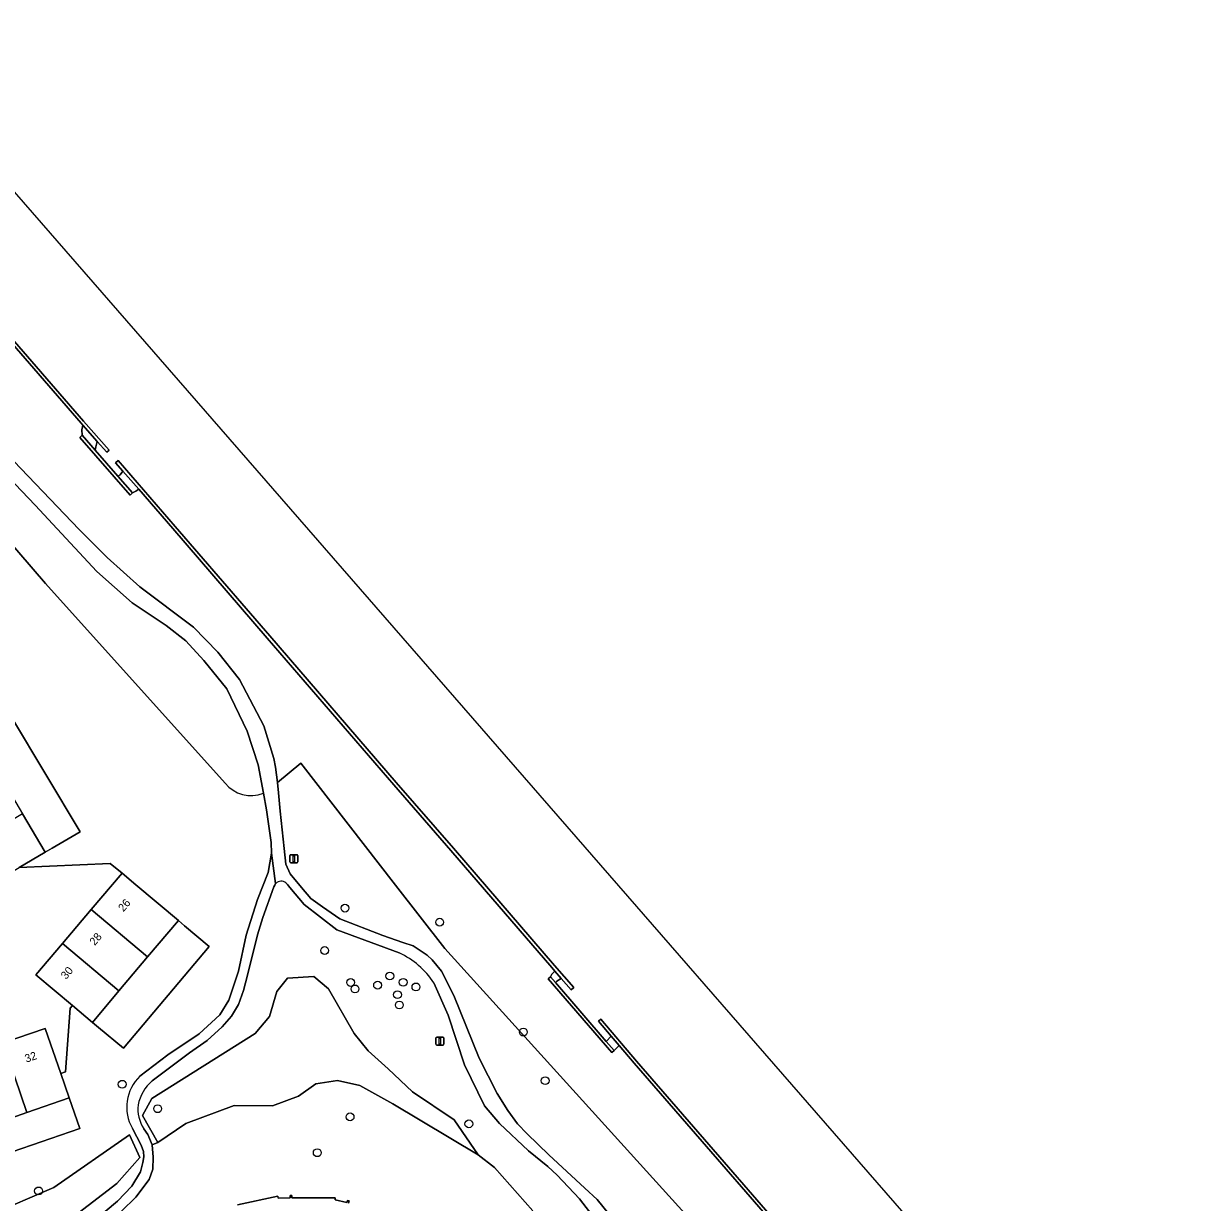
# Model space of a CAD drawing. Extents: x 156661 to 157576, y 383570 to 384425.
# Drawn here: x 157016.4 to 157162.1, y 384130.7 to 384278 of the extents above; entities that cross this region are included whole.
import ezdxf

# ---------------------------------------------------------------- set-up
doc = ezdxf.new("R2010")
doc.units = 0
for name, color, linetype in [('IMGEO_Afsluitpaal', 7, 'Continuous'), ('IMGEO_Boom', 7, 'Continuous'), ('IMGEO_Erf', 7, 'Continuous'), ('IMGEO_Greppel_droge_sloot', 7, 'Continuous'), ('IMGEO_Groenvoorziening', 7, 'Continuous'), ('IMGEO_Houtwal', 7, 'Continuous'), ('IMGEO_Kademuur', 7, 'Continuous'), ('IMGEO_Muur', 7, 'Continuous'), ('IMGEO_Oever', 7, 'Continuous'), ('IMGEO_Pand', 7, 'Continuous'), ('IMGEO_Pand_nummerreeks', 7, 'Continuous'), ('IMGEO_Verkeersbordpaal', 7, 'Continuous'), ('IMGEO_Voetpad_halfverhard', 7, 'Continuous'), ('IMGEO_Waterloop', 7, 'Continuous')]:
    doc.layers.add(name, color=color, linetype=linetype)

msp = doc.modelspace()

# ---------------------------------------------------------------- linework, layer by layer
at = {"layer": 'IMGEO_Afsluitpaal'}
for p, q in [((157067.89, 384150.45), (157067.89, 384151.24)), ((157067.89, 384151.24), (157067.89, 384150.45)), ((157067.99, 384151.34), (157068.78, 384151.34)), ((157068.78, 384151.34), (157067.99, 384151.34)), ((157068.78, 384150.35), (157067.99, 384150.35)), ((157067.99, 384150.35), (157068.78, 384150.35)), ((157068.88, 384151.24), (157068.88, 384150.45)), ((157068.88, 384150.45), (157068.88, 384151.24))]:
    msp.add_line(p, q, dxfattribs=at)
msp.add_lwpolyline([(157068.31, 384151.22), (157068.46, 384151.22), (157068.46, 384150.47), (157068.31, 384150.47), (157068.31, 384151.22)], dxfattribs=at)
for centre, start, end in [((157067.99, 384151.24), 90, 180), ((157067.99, 384151.24), 90, 180), ((157067.99, 384150.45), 180, 270), ((157067.99, 384150.45), 180, 270), ((157068.78, 384151.24), 0, 90), ((157068.78, 384151.24), 360, 90), ((157068.78, 384150.45), 270, 0), ((157068.78, 384150.45), 270, 0)]:
    msp.add_arc(centre, 0.1, start, end, dxfattribs=at)
at = {"layer": 'IMGEO_Boom'}
for centre in [(157056.52, 384167.47), (157068.36, 384165.71), (157053.98, 384162.17), (157062.13, 384158.98), (157057.24, 384158.18), (157057.77, 384157.37), (157060.6, 384157.84), (157063.8, 384158.2), (157065.39, 384157.62), (157063.08, 384156.65), (157063.31, 384155.36), (157078.82, 384151.98), (157028.68, 384145.46), (157081.55, 384145.9), (157033.11, 384142.4), (157057.16, 384141.38), (157072.01, 384140.51), (157053.06, 384136.9), (157018.23, 384132.13)]:
    msp.add_circle(centre, 0.489, dxfattribs=at)
at = {"layer": 'IMGEO_Erf'}
for points in [[(157010.52, 384188.78), (157013.37, 384184), (157016.22, 384179.24), (157019.06, 384174.47), (157019.93, 384174.98), (157023.41, 384177.02), (157014.84, 384191.35), (157011.39, 384189.29)], [(157025.73, 384152.55), (157028.83, 384149.97), (157039.56, 384162.69), (157036.48, 384165.27), (157035.7, 384165.92), (157031.86, 384161.37), (157028.28, 384157.12), (157024.96, 384153.19)], [(157006.66, 384137.36), (157007.65, 384134.51), (157023.4, 384139.95), (157022.39, 384142.82), (157022.06, 384143.77), (157016.78, 384141.93), (157011.54, 384140.11), (157006.33, 384138.3)]]:
    msp.add_lwpolyline(points, close=True, dxfattribs=at)
for points in [[(157013.79, 384150.62), (157019.05, 384152.43), (157021, 384146.82), (157021.59, 384147.02), (157022.19, 384154.96), (157022.46, 384155.29), (157017.9, 384159.12), (157021.23, 384163.05), (157024.82, 384167.28), (157028.66, 384171.82), (157027.18, 384173.06), (157015.79, 384172.54)], [(157056.97, 384130.62), (157057.03, 384130.89), (157056.82, 384130.94), (157056.77, 384130.67), (157055.29, 384131), (157055.3, 384131.25), (157049.9, 384131.27), (157049.89, 384131.54), (157049.69, 384131.54), (157049.69, 384131.27), (157048.19, 384131.21), (157048.13, 384131.48), (157043.1, 384130.38)]]:
    msp.add_lwpolyline(points, dxfattribs=at)
at = {"layer": 'IMGEO_Greppel_droge_sloot'}
for points in [[(157057.67, 384151.81), (157054.48, 384157.38), (157052.61, 384158.91), (157049.33, 384158.7), (157048.02, 384157.03), (157047.08, 384153.92), (157045.3, 384151.79), (157032.38, 384143.68), (157031.2, 384141.56), (157033.15, 384138.17), (157036.64, 384140.57), (157042.69, 384142.82), (157047.48, 384142.77), (157050.7, 384143.97), (157052.89, 384145.51), (157055.6, 384145.94), (157058.37, 384145.32), (157062.52, 384143.02), (157073.18, 384136.62), (157070.19, 384141.01), (157064.98, 384144.51), (157061.93, 384147.4), (157059.42, 384149.63)], [(157020.85, 384127.54), (157028.03, 384133.07), (157030.88, 384136.29), (157029.6, 384139.14), (157020.14, 384132.57), (157011.98, 384129.07), (157003.7, 384126.69), (156998.76, 384122.64), (157001.81, 384121.29), (157011.12, 384122.68)]]:
    msp.add_lwpolyline(points, close=True, dxfattribs=at)
at = {"layer": 'IMGEO_Groenvoorziening'}
for points in [[(157041.54, 384183.09), (157019.08, 384208.03), (157004.98, 384224.39)], [(157014.84, 384191.35), (157023.41, 384177.02), (157019.93, 384174.98), (157019.06, 384174.47), (157015.79, 384172.54), (157027.18, 384173.06), (157028.66, 384171.82), (157030.4, 384170.36), (157035.7, 384165.92), (157036.48, 384165.27), (157039.56, 384162.69), (157028.83, 384149.97), (157025.73, 384152.55), (157024.96, 384153.19), (157022.46, 384155.29), (157022.19, 384154.96), (157021.59, 384147.02), (157021, 384146.82), (157022.06, 384143.77), (157022.39, 384142.82), (157023.4, 384139.95), (157007.65, 384134.51)], [(157107.42, 384120.01), (157068.99, 384162.42), (157062.85, 384170.34), (157051.02, 384185.6), (157048.07, 384183.16), (157048.23, 384181.88), (157048.43, 384179.6), (157048.92, 384174.93), (157049.15, 384172.98), (157049.67, 384171.76), (157051.08, 384170.04), (157052.24, 384168.68), (157053.73, 384167.61), (157055.86, 384166.15), (157061.25, 384164.03), (157063.77, 384163.18), (157065.06, 384162.74), (157065.94, 384162.17), (157066.81, 384161.58), (157067.44, 384161), (157068.6, 384159.57), (157070.14, 384156.57), (157073.28, 384148.7), (157075.53, 384144.3), (157076.88, 384142.2), (157078.09, 384140.5), (157079.31, 384139.27), (157082.01, 384136.66), (157086.51, 384132.48), (157088.05, 384131.05), (157091.04, 384127.35)], [(157030.9, 384146.49), (157034.38, 384149.12), (157038.31, 384151.74), (157040.89, 384154.15), (157042.01, 384155.98), (157043.22, 384159.6), (157044.19, 384164.08), (157045.6, 384168.56), (157046.91, 384171.94), (157047.33, 384174.35), (157047.28, 384175.68), (157046.71, 384179.73), (157046.32, 384181.83)], [(157063.29, 384161.87), (157055.52, 384164.74), (157051.44, 384167.93), (157049.63, 384170.05), (157049.48, 384170.25), (157049.32, 384170.44), (157049.14, 384170.61)], [(157047.86, 384170.54), (157047.74, 384170.34), (157047.65, 384170.11), (157046.26, 384166.31), (157045.57, 384164.15), (157044.32, 384159.07), (157043.82, 384157.18), (157043.23, 384155.44), (157042.36, 384153.96), (157041.18, 384152.62), (157039.28, 384150.91), (157037.1, 384149.38), (157032.43, 384145.87)], [(157031.39, 384139.9), (157031.89, 384139.17), (157032.41, 384137.9), (157033.15, 384138.17), (157031.2, 384141.56), (157032.38, 384143.68), (157045.3, 384151.79), (157047.08, 384153.92), (157048.02, 384157.03), (157049.33, 384158.7), (157052.61, 384158.91), (157054.48, 384157.38), (157057.67, 384151.81), (157059.42, 384149.63), (157061.93, 384147.4), (157064.98, 384144.51), (157070.19, 384141.01), (157073.18, 384136.62), (157075.19, 384135.05), (157079.98, 384129.64)], [(157209, 383933.11), (157208.19, 383936.36), (157188.23, 383963.43), (157190.29, 383965.09), (157189.95, 383965.49), (157191.63, 383966.17), (157192.42, 383966.8), (157192.61, 383966.56), (157193.69, 383967), (157194.04, 383967.21), (157214.31, 383979.84), (157095.74, 384121.39), (157093.38, 384123.17), (157089.79, 384126.55), (157087.81, 384128.62), (157085.82, 384131.16), (157083.05, 384134.11), (157081.87, 384135.17), (157079.45, 384137.14), (157075.84, 384140.54), (157073.95, 384142.77), (157071.48, 384147.87), (157069.43, 384154.1), (157067.64, 384158.13)], [(157079.98, 384129.64), (157075.19, 384135.05), (157073.18, 384136.62), (157062.52, 384143.02), (157058.37, 384145.32), (157055.6, 384145.94), (157052.89, 384145.51), (157050.7, 384143.97), (157047.48, 384142.77), (157042.69, 384142.82), (157036.64, 384140.57), (157033.15, 384138.17), (157032.41, 384137.9), (157032.57, 384136.35), (157032.5, 384134.85), (157032.04, 384133.57), (157030.38, 384131.36), (157028.58, 384129.59)], [(157026.54, 384129.57), (157028.08, 384130.85), (157029.89, 384132.74), (157030.96, 384134.5), (157031.27, 384135.67), (157031.39, 384136.4), (157031.33, 384137.04), (157031.04, 384137.85), (157029.96, 384139.92)], [(157043.1, 384130.38), (157048.13, 384131.48), (157048.19, 384131.21), (157049.69, 384131.27), (157049.69, 384131.54), (157049.89, 384131.54), (157049.9, 384131.27), (157055.3, 384131.25), (157055.29, 384131), (157056.77, 384130.67), (157056.82, 384130.94), (157057.03, 384130.89), (157056.97, 384130.62)]]:
    msp.add_lwpolyline(points, dxfattribs=at)
msp.add_lwpolyline([(157029.6, 384139.14), (157030.88, 384136.29), (157028.03, 384133.07), (157020.85, 384127.54), (157011.12, 384122.68), (157001.81, 384121.29), (156998.76, 384122.64), (157003.7, 384126.69), (157011.98, 384129.07), (157020.14, 384132.57)], close=True, dxfattribs=at)
for centre, radius, start, end in [((157044.79, 384185.72), 4.18, 218.9328, 291.4834), ((157048.54, 384169.89), 0.946, 49.9408, 135.8417), ((157059, 384152.47), 10.33, 33.2185, 65.4401), ((157034.62, 384142.6), 5.38, 133.7652, 209.9038), ((157035.46, 384142.09), 4.84, 128.6864, 170.7152), ((157034.95, 384142.33), 4.31, 172.705, 214.2296)]:
    msp.add_arc(centre, radius, start, end, dxfattribs=at)
at = {"layer": 'IMGEO_Houtwal'}
for points in [[(156978.72, 384262.51), (156978.51, 384262.21), (156980.47, 384260.7), (156984.68, 384256.94), (156997.37, 384244.41), (157013.26, 384225.25), (157023.32, 384214.78), (157026.81, 384211.27), (157030.88, 384207.6), (157037.59, 384202.58), (157040.64, 384199.44), (157043.35, 384196.04), (157046.38, 384190.23), (157047.65, 384186.15), (157047.82, 384185.09), (157048.07, 384183.16), (157051.02, 384185.6), (157062.85, 384170.34), (157068.99, 384162.42), (157107.42, 384120.01)], [(156978.29, 384256.96), (156980.17, 384254.98), (156984.21, 384250), (157000, 384230.52), (157004.98, 384224.39), (157019.08, 384208.03), (157041.54, 384183.09)], [(157092.65, 384148.1), (157090.78, 384150.3), (157090.16, 384149.67), (157089.86, 384149.41), (157081.91, 384158.64), (157082.21, 384158.9), (157082.37, 384159.22), (157082.75, 384159.6), (157082.37, 384160.03), (157069.77, 384174.67), (157062.62, 384182.87), (157046.8, 384201.21), (157035, 384214.9), (157030.74, 384219.81), (157030.39, 384219.58), (157029.97, 384219.35), (157029.67, 384219.09), (157023.37, 384226.29), (157023.67, 384226.55), (157023.63, 384227.22), (157023.76, 384227.8), (157023.54, 384228.05), (157006.01, 384248.27)], [(157046.32, 384181.83), (157045.67, 384185.37), (157044.28, 384189.57), (157041.77, 384194.89), (157038.88, 384198.43), (157036.64, 384200.85), (157034.17, 384202.8), (157029.91, 384205.62), (157025.53, 384209.53), (157017.8, 384217.82), (157012.72, 384223.1), (157008.16, 384228.71), (157001.14, 384237.04)], [(157171.11, 384059.37), (157158.6, 384073.63), (157144.69, 384089.56), (157142.02, 384092.64), (157141.55, 384092.17), (157141.27, 384091.91), (157140.97, 384091.65), (157133.88, 384099.48), (157134.17, 384099.75), (157134.46, 384100.25), (157134.81, 384100.59), (157124.55, 384112.04), (157122.54, 384113.64), (157114.25, 384123.21), (157103.63, 384135.48), (157092.65, 384148.1)]]:
    msp.add_lwpolyline(points, dxfattribs=at)
msp.add_arc((157044.79, 384185.72), 4.18, 218.9328, 291.4834, dxfattribs=at)
at = {"layer": 'IMGEO_Kademuur'}
for points in [[(157006.31, 384248.53), (156993.04, 384263.6), (156992.33, 384266.34), (156983.82, 384276.03), (156962.6, 384300.36), (156939.02, 384327.5), (156926.02, 384342.63), (156925.56, 384342.27), (156926.89, 384340.7), (156928.32, 384339.01), (156928.69, 384338.92), (156938.72, 384327.24), (156962.3, 384300.1), (156983.52, 384275.77), (156991.97, 384266.15), (156992.67, 384263.41), (157006.01, 384248.27), (157023.54, 384228.05), (157023.76, 384227.8), (157025.56, 384225.77), (157026.74, 384224.43), (157027.04, 384224.69), (157023.85, 384228.32)], [(157025.3, 384224.69), (157023.67, 384226.55), (157023.37, 384226.29), (157029.67, 384219.09), (157029.97, 384219.35), (157028.13, 384221.45)], [(157082.69, 384160.31), (157070.08, 384174.95), (157062.93, 384183.15), (157047.12, 384201.48), (157035.32, 384215.17), (157028.18, 384223.4), (157027.86, 384223.12), (157028.77, 384222.07), (157030.74, 384219.81), (157035, 384214.9), (157046.8, 384201.21), (157062.62, 384182.87), (157069.77, 384174.67), (157082.37, 384160.03), (157082.75, 384159.6), (157083.55, 384158.69), (157084.8, 384157.26), (157085.11, 384157.54)], [(157082.85, 384158.16), (157082.21, 384158.9), (157081.91, 384158.64), (157089.86, 384149.41), (157090.16, 384149.67), (157089.18, 384150.81)], [(157124.83, 384112.33), (157122.82, 384113.93), (157114.55, 384123.47), (157103.93, 384135.74), (157092.96, 384148.36), (157088.5, 384153.61), (157088.19, 384153.35), (157089.81, 384151.45), (157090.78, 384150.3), (157092.65, 384148.1), (157103.63, 384135.48), (157114.25, 384123.21), (157122.54, 384113.64), (157124.55, 384112.04), (157134.81, 384100.59), (157134.82, 384100.58), (157137.1, 384097.95), (157137.76, 384097.18), (157137.92, 384097.19), (157138.22, 384097.46)]]:
    msp.add_lwpolyline(points, close=True, dxfattribs=at)
at = {"layer": 'IMGEO_Muur'}
for points in [[(157011.39, 384189.29), (157014.84, 384191.35), (157023.41, 384177.02), (157019.93, 384174.98)], [(157019.06, 384174.47), (157019.93, 384174.98)], [(157025.73, 384152.55), (157028.83, 384149.97), (157039.56, 384162.69), (157036.48, 384165.27)], [(157035.7, 384165.92), (157036.48, 384165.27)], [(157024.96, 384153.19), (157025.73, 384152.55)], [(157022.39, 384142.82), (157023.4, 384139.95), (157007.65, 384134.51), (157006.66, 384137.36)], [(157022.06, 384143.77), (157022.39, 384142.82)]]:
    msp.add_lwpolyline(points, dxfattribs=at)
at = {"layer": 'IMGEO_Oever'}
for points in [[(157023.76, 384227.8), (157023.63, 384227.22), (157023.67, 384226.55), (157025.3, 384224.69), (157025.38, 384225.1), (157025.56, 384225.77)], [(157028.77, 384222.07), (157028.43, 384221.62), (157028.13, 384221.45), (157029.97, 384219.35), (157030.39, 384219.58), (157030.74, 384219.81)], [(157082.75, 384159.6), (157082.37, 384159.22), (157082.21, 384158.9), (157082.85, 384158.16), (157083.01, 384158.36), (157083.55, 384158.69)], [(157089.81, 384151.45), (157089.18, 384150.81), (157090.16, 384149.67), (157090.78, 384150.3)]]:
    msp.add_lwpolyline(points, close=True, dxfattribs=at)
at = {"layer": 'IMGEO_Pand'}
for points in [[(157008.29, 384174.54), (157011.12, 384169.78), (157015.79, 384172.54), (157019.06, 384174.47), (157016.22, 384179.24)], [(157031.86, 384161.37), (157035.7, 384165.92), (157030.4, 384170.36), (157028.66, 384171.82), (157024.82, 384167.28)], [(157031.86, 384161.37), (157024.82, 384167.28), (157021.23, 384163.05), (157028.28, 384157.12)], [(157021.23, 384163.05), (157017.9, 384159.12), (157022.46, 384155.29), (157024.96, 384153.19), (157028.28, 384157.12)], [(157016.78, 384141.93), (157022.06, 384143.77), (157021, 384146.82), (157019.05, 384152.43), (157013.79, 384150.62)], [(157016.78, 384141.93), (157013.79, 384150.62), (157008.54, 384148.81), (157011.54, 384140.11)]]:
    msp.add_lwpolyline(points, close=True, dxfattribs=at)
at = {"layer": 'IMGEO_Verkeersbordpaal'}
for p, q in [((157049.64, 384173.24), (157049.64, 384174.04)), ((157049.64, 384174.04), (157049.64, 384173.24)), ((157049.74, 384174.14), (157050.53, 384174.14)), ((157050.53, 384174.14), (157049.74, 384174.14)), ((157050.63, 384174.04), (157050.63, 384173.24)), ((157050.63, 384173.24), (157050.63, 384174.04)), ((157050.53, 384173.14), (157049.74, 384173.14)), ((157049.74, 384173.14), (157050.53, 384173.14))]:
    msp.add_line(p, q, dxfattribs=at)
msp.add_lwpolyline([(157050.06, 384174.02), (157050.21, 384174.02), (157050.21, 384173.27), (157050.06, 384173.27), (157050.06, 384174.02)], dxfattribs=at)
for centre, start, end in [((157049.74, 384174.04), 90, 180), ((157049.74, 384174.04), 90, 180), ((157050.53, 384174.04), 0, 90), ((157050.53, 384174.04), 360, 90), ((157049.74, 384173.24), 180, 270), ((157049.74, 384173.24), 180, 270), ((157050.53, 384173.24), 270, 0), ((157050.53, 384173.24), 270, 0)]:
    msp.add_arc(centre, 0.1, start, end, dxfattribs=at)
at = {"layer": 'IMGEO_Voetpad_halfverhard'}
for points in [[(157091.04, 384127.35), (157088.05, 384131.05), (157086.51, 384132.48), (157082.01, 384136.66), (157079.31, 384139.27), (157078.09, 384140.5), (157076.88, 384142.2), (157075.53, 384144.3), (157073.28, 384148.7), (157070.14, 384156.57), (157068.6, 384159.57), (157067.44, 384161), (157066.81, 384161.58), (157065.94, 384162.17), (157065.06, 384162.74), (157063.77, 384163.18), (157061.25, 384164.03), (157055.86, 384166.15), (157053.73, 384167.61), (157052.24, 384168.68), (157051.08, 384170.04), (157049.67, 384171.76), (157049.15, 384172.98), (157048.92, 384174.93), (157048.43, 384179.6), (157048.23, 384181.88), (157048.07, 384183.16), (157047.82, 384185.09), (157047.65, 384186.15), (157046.38, 384190.23), (157043.35, 384196.04), (157040.64, 384199.44), (157037.59, 384202.58), (157030.88, 384207.6), (157026.81, 384211.27), (157023.32, 384214.78), (157013.26, 384225.25)], [(157012.72, 384223.1), (157017.8, 384217.82), (157025.53, 384209.53), (157029.91, 384205.62), (157034.17, 384202.8), (157036.64, 384200.85), (157038.88, 384198.43), (157041.77, 384194.89), (157044.28, 384189.57), (157045.67, 384185.37), (157046.32, 384181.83), (157046.71, 384179.73), (157047.28, 384175.68), (157047.33, 384174.35), (157047.86, 384170.54)], [(157046.26, 384166.31), (157047.65, 384170.11), (157047.74, 384170.34), (157047.86, 384170.54), (157047.33, 384174.35), (157046.91, 384171.94), (157045.6, 384168.56), (157044.19, 384164.08), (157043.22, 384159.6), (157042.01, 384155.98), (157040.89, 384154.15), (157038.31, 384151.74), (157034.38, 384149.12), (157030.9, 384146.49)], [(157049.14, 384170.61), (157049.32, 384170.44), (157049.48, 384170.25), (157049.63, 384170.05), (157051.44, 384167.93), (157055.52, 384164.74), (157063.29, 384161.87)], [(157032.43, 384145.87), (157037.1, 384149.38), (157039.28, 384150.91), (157041.18, 384152.62), (157042.36, 384153.96), (157043.23, 384155.44), (157043.82, 384157.18), (157044.32, 384159.07), (157045.57, 384164.15), (157046.26, 384166.31)], [(157067.64, 384158.13), (157069.43, 384154.1), (157071.48, 384147.87), (157073.95, 384142.77), (157075.84, 384140.54), (157079.45, 384137.14), (157081.87, 384135.17), (157083.05, 384134.11), (157085.82, 384131.16), (157087.81, 384128.62)], [(157029.96, 384139.92), (157031.04, 384137.85), (157031.33, 384137.04), (157031.39, 384136.4), (157031.27, 384135.67), (157030.96, 384134.5), (157029.89, 384132.74), (157028.08, 384130.85), (157026.54, 384129.57)], [(157028.58, 384129.59), (157030.38, 384131.36), (157032.04, 384133.57), (157032.5, 384134.85), (157032.57, 384136.35), (157032.41, 384137.9), (157031.89, 384139.17), (157031.39, 384139.9)]]:
    msp.add_lwpolyline(points, dxfattribs=at)
for centre, radius, start, end in [((157048.54, 384169.89), 0.946, 49.9408, 135.8417), ((157059, 384152.47), 10.33, 33.2185, 65.4401), ((157034.62, 384142.6), 5.38, 133.7652, 209.9038), ((157035.46, 384142.09), 4.84, 128.6864, 170.7152), ((157034.95, 384142.33), 4.31, 172.705, 214.2296)]:
    msp.add_arc(centre, radius, start, end, dxfattribs=at)
at = {"layer": 'IMGEO_Waterloop'}
for points in [[(157335.95, 383888.66), (157157.55, 384093.52), (156868.63, 384425.31)], [(157006.31, 384248.53), (157023.85, 384228.32), (157027.04, 384224.69), (157026.74, 384224.43), (157025.56, 384225.77), (157025.38, 384225.1), (157025.3, 384224.69), (157028.13, 384221.45), (157028.43, 384221.62), (157028.77, 384222.07), (157027.86, 384223.12), (157028.18, 384223.4), (157035.32, 384215.17), (157047.12, 384201.48), (157062.93, 384183.15), (157070.08, 384174.95), (157082.69, 384160.31), (157085.11, 384157.54), (157084.8, 384157.26), (157083.55, 384158.69), (157083.01, 384158.36), (157082.85, 384158.16), (157089.18, 384150.81), (157089.81, 384151.45), (157088.19, 384153.35), (157088.5, 384153.61), (157092.96, 384148.36), (157103.93, 384135.74), (157114.55, 384123.47)]]:
    msp.add_lwpolyline(points, dxfattribs=at)

# ---------------------------------------------------------------- texts
at = {"layer": 'IMGEO_Pand_nummerreeks'}
for s, rotation, p in [('26', 49.7297, (157028.84, 384166.95)), ('28', 49.7297, (157025.25, 384162.72)), ('30', 49.7297, (157021.67, 384158.49)), ('32', 18.9819, (157016.7, 384148.15))]:
    msp.add_text(s, height=1, rotation=rotation, dxfattribs=at).set_placement(p)

doc.saveas('drawing.dxf')
